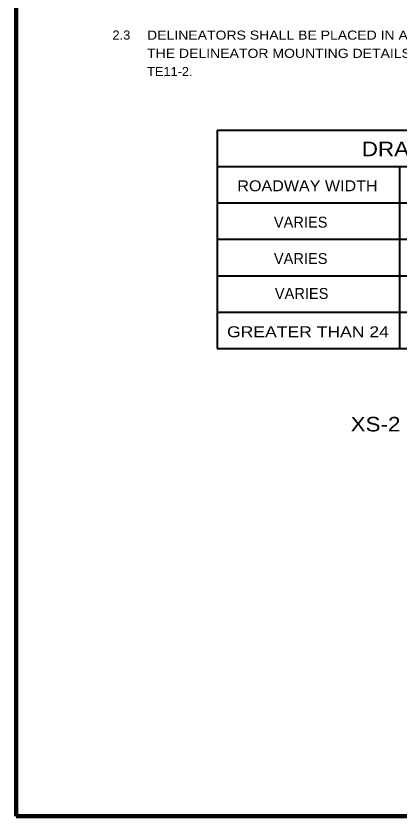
# Model space of a CAD drawing. Extents: x -1843 to -987, y 1073 to 1617.
# Drawn here: x -1785.5 to -1659.1, y 1084.3 to 1347.9 of the extents above; entities that cross this region are included whole.
import ezdxf
from ezdxf.enums import TextEntityAlignment as Align

# ---------------------------------------------------------------- set-up
doc = ezdxf.new("R2010")
doc.units = 0
doc.header["$LTSCALE"] = 1.2
doc.layers.add('1', color=7, linetype='Continuous', lineweight=53)

msp = doc.modelspace()

# ---------------------------------------------------------------- linework, layer by layer
at = {"layer": '1', "lineweight": 40}
for p, q in [((-1719.272, 1310.333), (-1539.272, 1310.333)), ((-1719.272, 1310.333), (-1719.272, 1238.333)), ((-1719.272, 1298.333), (-1539.272, 1298.333)), ((-1659.272, 1298.333), (-1659.272, 1238.333)), ((-1719.272, 1286.333), (-1539.272, 1286.333)), ((-1719.272, 1274.333), (-1539.272, 1274.333)), ((-1719.272, 1262.333), (-1539.272, 1262.333)), ((-1719.272, 1250.333), (-1539.272, 1250.333)), ((-1719.272, 1238.333), (-1539.272, 1238.333))]:
    msp.add_line(p, q, dxfattribs=at)
at = {"layer": '1', "lineweight": 158}
msp.add_line((-993.822, 1084.318), (-1785.422, 1084.318), dxfattribs=at)
msp.add_lwpolyline([(-993.822, 1610.418), (-1785.522, 1610.318), (-1785.422, 1084.318)], dxfattribs=at)

# ---------------------------------------------------------------- texts
at = {"layer": '1'}
for s, width, p in [('2.3', 1.05, (-1753.752, 1340.11)), ('DELINEATORS SHALL BE PLACED IN AN ALIGNMENT IN ACCORDANCE WITH DRAWINGS AS SHOWN.', 1.15, (-1742.363, 1340.094)), ('THE DELINEATOR MOUNTING DETAILS ARE SHOWN ON STANDARD DETAIL SHEETS TE11-1 AND', 1.15, (-1742.363, 1334.094)), ('TE11-2.', 1.05, (-1742.363, 1328.094))]:
    msp.add_text(s, height=3, dxfattribs=dict(at, width=width)).set_placement(p)
for s, height, width, p in [('DRAWING TO BE USED', 4.8, 1.15, (-1630.434, 1301.701)), ('ROADWAY WIDTH', 3.6, 1.1, (-1689.54, 1290.156)), ('GREATER THAN 24', 3.6, 1.2, (-1689.381, 1242.057)), ('XS-2', 4.8, 1.15, (-1667.125, 1211.022))]:
    msp.add_text(s, height=height, dxfattribs=dict(at, width=width)).set_placement(p, align=Align.CENTER)
for p in [(-1691.777, 1278.171), (-1691.777, 1266.186), (-1691.457, 1254.681)]:
    msp.add_text('VARIES', height=3.6, dxfattribs=at).set_placement(p, align=Align.CENTER)

doc.saveas('drawing.dxf')
